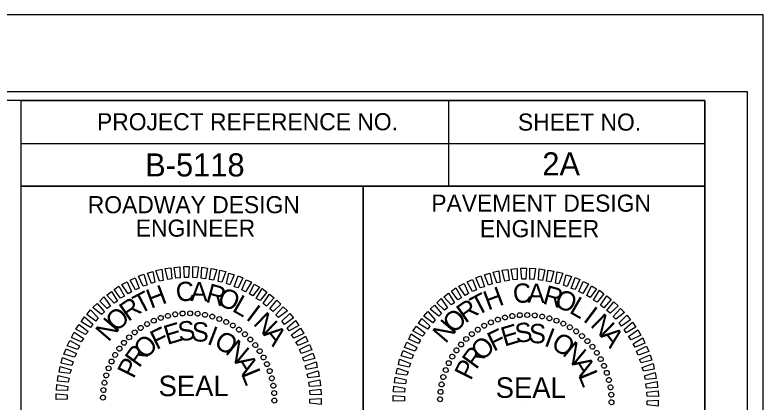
# Model space of a CAD drawing. Extents: x 575722 to 576066, y -53107 to -52774.
# Drawn here: x 575943.89 to 575965.78, y -53008.18 to -52996.87 of the extents above; entities that cross this region are included whole.
import ezdxf

# ---------------------------------------------------------------- set-up
doc = ezdxf.new("R2010")
doc.units = 0
for name, color, linetype in [('Sheet Cutting Line CELL', 7, 'Continuous'), ('Sheet Data Field CELL', 7, 'Continuous'), ('Sheet PE Seal Cell', 7, 'Continuous'), ('Sheet Plot Border Inside CELL', 7, 'Continuous'), ('Sheet Plot Border Outside CELL', 7, 'Continuous'), ('Sheet Professional Seal CELL', 7, 'Continuous'), ('Sheet Typical CELL', 7, 'Continuous')]:
    doc.layers.add(name, color=color, linetype=linetype)

msp = doc.modelspace()

# ---------------------------------------------------------------- linework, layer by layer
at = {"layer": 'Sheet Cutting Line CELL'}
msp.add_line((575965.78, -52996.867), (575797.38, -52996.867), dxfattribs=at)
at = {"layer": 'Sheet PE Seal Cell'}
for p, q in [((575958.019, -53005.768), (575958.019, -53005.768)), ((575958.229, -53005.708), (575958.229, -53005.708)), ((575958.449, -53005.668), (575958.449, -53005.668)), ((575958.664, -53005.638), (575958.664, -53005.638)), ((575958.884, -53005.633), (575958.884, -53005.633)), ((575959.104, -53005.648), (575959.104, -53005.648)), ((575959.319, -53005.683), (575959.319, -53005.683)), ((575959.529, -53005.728), (575959.529, -53005.728)), ((575957.624, -53005.948), (575957.624, -53005.948)), ((575957.819, -53005.848), (575957.819, -53005.848)), ((575959.739, -53005.798), (575959.739, -53005.798)), ((575959.939, -53005.888), (575959.939, -53005.888)), ((575957.259, -53006.188), (575957.259, -53006.188)), ((575957.434, -53006.063), (575957.434, -53006.063)), ((575960.134, -53005.988), (575960.134, -53005.988)), ((575960.314, -53006.113), (575960.314, -53006.113)), ((575957.094, -53006.338), (575957.094, -53006.338)), ((575960.489, -53006.248), (575960.489, -53006.248)), ((575960.644, -53006.398), (575960.644, -53006.398)), ((575956.944, -53006.493), (575956.944, -53006.493)), ((575960.794, -53006.563), (575960.794, -53006.563)), ((575956.684, -53006.848), (575956.684, -53006.848)), ((575956.809, -53006.668), (575956.809, -53006.668)), ((575960.919, -53006.738), (575960.919, -53006.738)), ((575956.584, -53007.043), (575956.584, -53007.043)), ((575961.034, -53006.928), (575961.034, -53006.928)), ((575956.494, -53007.243), (575956.494, -53007.243)), ((575961.134, -53007.123), (575961.134, -53007.123)), ((575956.424, -53007.453), (575956.424, -53007.453)), ((575961.214, -53007.323), (575961.214, -53007.323)), ((575956.379, -53007.663), (575956.379, -53007.663)), ((575961.274, -53007.533), (575961.274, -53007.533)), ((575956.344, -53007.878), (575956.344, -53007.878)), ((575961.314, -53007.753), (575961.314, -53007.753)), ((575956.329, -53008.098), (575956.329, -53008.098)), ((575958.839, -53008.143), (575958.839, -53008.143)), ((575961.344, -53007.968), (575961.344, -53007.968))]:
    msp.add_line(p, q, dxfattribs=at)
for points in [[(575957.749, -53004.763), (575957.634, -53004.463), (575957.789, -53004.418), (575957.854, -53004.728)], [(575957.989, -53004.698), (575957.884, -53004.383), (575958.054, -53004.348), (575958.094, -53004.673)], [(575958.229, -53004.643), (575958.149, -53004.323), (575958.314, -53004.308), (575958.349, -53004.628)], [(575958.469, -53004.613), (575958.414, -53004.293), (575958.584, -53004.273), (575958.589, -53004.598)], [(575958.719, -53004.588), (575958.694, -53004.263), (575958.859, -53004.268), (575958.839, -53004.593)], [(575958.959, -53004.593), (575958.959, -53004.268), (575959.124, -53004.273), (575959.079, -53004.598)], [(575959.209, -53004.608), (575959.229, -53004.283), (575959.394, -53004.313), (575959.329, -53004.628)], [(575959.449, -53004.648), (575959.494, -53004.328), (575959.659, -53004.353), (575959.569, -53004.663)], [(575959.704, -53004.703), (575959.754, -53004.378), (575959.924, -53004.418), (575959.809, -53004.728)], [(575957.284, -53004.948), (575957.124, -53004.668), (575957.279, -53004.598), (575957.394, -53004.903)], [(575957.504, -53004.843), (575957.374, -53004.553), (575957.524, -53004.493), (575957.629, -53004.813)], [(575959.944, -53004.768), (575960.019, -53004.458), (575960.174, -53004.508), (575960.049, -53004.803)], [(575960.169, -53004.858), (575960.284, -53004.543), (575960.424, -53004.603), (575960.284, -53004.893)], [(575960.394, -53004.953), (575960.519, -53004.658), (575960.674, -53004.728), (575960.504, -53005.008)], [(575956.849, -53005.193), (575956.664, -53004.938), (575956.794, -53004.843), (575956.959, -53005.133)], [(575957.069, -53005.068), (575956.884, -53004.798), (575957.039, -53004.718), (575957.164, -53005.008)], [(575960.624, -53005.068), (575960.759, -53004.783), (575960.909, -53004.868), (575960.719, -53005.128)], [(575956.659, -53005.343), (575956.444, -53005.103), (575956.579, -53004.998), (575956.754, -53005.278)], [(575960.819, -53005.203), (575960.994, -53004.913), (575961.124, -53005.018), (575960.929, -53005.263)], [(575961.024, -53005.353), (575961.209, -53005.078), (575961.339, -53005.188), (575961.119, -53005.423)], [(575956.459, -53005.498), (575956.239, -53005.278), (575956.359, -53005.158), (575956.554, -53005.428)], [(575961.214, -53005.508), (575961.419, -53005.248), (575961.539, -53005.368), (575961.309, -53005.583)], [(575956.119, -53005.863), (575955.859, -53005.668), (575955.969, -53005.538), (575956.189, -53005.773)], [(575956.294, -53005.673), (575956.039, -53005.468), (575956.164, -53005.353), (575956.374, -53005.593)], [(575961.394, -53005.683), (575961.609, -53005.448), (575961.729, -53005.568), (575961.469, -53005.763)], [(575955.969, -53006.053), (575955.699, -53005.883), (575955.794, -53005.738), (575956.034, -53005.958)], [(575961.569, -53005.863), (575961.799, -53005.638), (575961.904, -53005.773), (575961.639, -53005.963)], [(575955.819, -53006.253), (575955.539, -53006.103), (575955.639, -53005.963), (575955.899, -53006.163)], [(575961.719, -53006.058), (575961.964, -53005.848), (575962.059, -53005.993), (575961.779, -53006.153)], [(575955.699, -53006.468), (575955.414, -53006.343), (575955.489, -53006.188), (575955.759, -53006.373)], [(575961.849, -53006.263), (575962.114, -53006.073), (575962.209, -53006.223), (575961.919, -53006.363)], [(575961.979, -53006.483), (575962.259, -53006.308), (575962.324, -53006.463), (575962.039, -53006.578)], [(575955.599, -53006.698), (575955.289, -53006.583), (575955.364, -53006.428), (575955.649, -53006.588)], [(575962.079, -53006.698), (575962.374, -53006.548), (575962.439, -53006.708), (575962.129, -53006.808)], [(575955.499, -53006.918), (575955.189, -53006.828), (575955.254, -53006.673), (575955.554, -53006.813)], [(575962.169, -53006.933), (575962.474, -53006.803), (575962.529, -53006.958), (575962.219, -53007.038)], [(575955.424, -53007.158), (575955.114, -53007.093), (575955.149, -53006.928), (575955.464, -53007.053)], [(575962.249, -53007.173), (575962.569, -53007.058), (575962.599, -53007.223), (575962.284, -53007.278)], [(575955.359, -53007.398), (575955.049, -53007.358), (575955.084, -53007.188), (575955.399, -53007.293)], [(575955.319, -53007.653), (575954.999, -53007.623), (575955.019, -53007.453), (575955.344, -53007.533)], [(575962.309, -53007.413), (575962.624, -53007.318), (575962.654, -53007.488), (575962.339, -53007.518)], [(575955.294, -53007.893), (575954.969, -53007.883), (575954.979, -53007.718), (575955.304, -53007.773)], [(575962.354, -53007.653), (575962.679, -53007.583), (575962.694, -53007.753), (575962.374, -53007.773)], [(575962.384, -53007.893), (575962.709, -53007.853), (575962.719, -53008.023), (575962.394, -53008.013)], [(575955.289, -53008.143), (575954.964, -53008.158), (575954.964, -53007.988), (575955.289, -53008.023)], [(575962.389, -53008.143), (575962.714, -53008.128), (575962.714, -53008.298), (575962.389, -53008.263)]]:
    msp.add_lwpolyline(points, close=True, dxfattribs=at)
for centre, major_axis in [((575958.022, -53005.772), (-0.0234, 0.0681)), ((575958.232, -53005.71), (-0.0174, 0.0699)), ((575958.447, -53005.666), (-0.0113, 0.0711)), ((575958.664, -53005.641), (-0.005, 0.0718)), ((575958.883, -53005.636), (0.0013, 0.072)), ((575959.101, -53005.649), (0.0075, 0.0716)), ((575959.317, -53005.681), (0.0137, 0.0707)), ((575959.53, -53005.733), (0.0198, 0.0692)), ((575959.738, -53005.802), (0.0258, 0.0672)), ((575957.436, -53006.064), (-0.0403, 0.0597)), ((575957.623, -53005.95), (-0.0349, 0.063)), ((575957.819, -53005.852), (-0.0293, 0.0658)), ((575959.938, -53005.889), (0.0316, 0.0647)), ((575960.131, -53005.994), (0.0371, 0.0617)), ((575957.261, -53006.194), (-0.0453, 0.056)), ((575960.313, -53006.114), (0.0423, 0.0582)), ((575960.484, -53006.251), (0.0472, 0.0543)), ((575956.946, -53006.498), (-0.0543, 0.0472)), ((575957.097, -53006.339), (-0.05, 0.0518)), ((575960.643, -53006.401), (0.0518, 0.05)), ((575956.81, -53006.669), (-0.0582, 0.0423)), ((575960.788, -53006.565), (0.056, 0.0453)), ((575956.689, -53006.852), (-0.0617, 0.0371)), ((575960.918, -53006.741), (0.0597, 0.0403)), ((575961.032, -53006.927), (0.063, 0.0349)), ((575956.585, -53007.044), (-0.0647, 0.0316)), ((575961.13, -53007.123), (0.0658, 0.0293)), ((575956.498, -53007.245), (-0.0672, 0.0258)), ((575961.21, -53007.327), (0.0681, 0.0234)), ((575956.428, -53007.452), (-0.0692, 0.0198)), ((575961.272, -53007.537), (0.0699, 0.0174)), ((575956.377, -53007.665), (-0.0707, 0.0137)), ((575961.316, -53007.751), (0.0711, 0.0113)), ((575956.345, -53007.881), (-0.0716, 0.0075)), ((575961.341, -53007.968), (0.0718, 0.005)), ((575956.331, -53008.1), (-0.072, 0.0013)), ((575961.347, -53008.187), (0.072, -0.0013))]:
    msp.add_ellipse(centre, major_axis=major_axis, ratio=0.999708, dxfattribs=at)
at = {"layer": 'Sheet Plot Border Inside CELL'}
msp.add_lwpolyline([(575965.33, -52999.112), (575798.68, -52999.112), (575798.68, -53104.622), (575965.33, -53104.622)], close=True, dxfattribs=at)
at = {"layer": 'Sheet Plot Border Outside CELL'}
msp.add_lwpolyline([(575965.78, -52996.867), (575797.38, -52996.867), (575797.38, -53106.867), (575965.78, -53106.867)], close=True, dxfattribs=at)
at = {"layer": 'Sheet Professional Seal CELL'}
for p, q in [((575948.156, -53005.719), (575948.156, -53005.719)), ((575948.366, -53005.659), (575948.366, -53005.659)), ((575948.586, -53005.619), (575948.586, -53005.619)), ((575948.801, -53005.589), (575948.801, -53005.589)), ((575949.021, -53005.584), (575949.021, -53005.584)), ((575949.241, -53005.599), (575949.241, -53005.599)), ((575949.456, -53005.634), (575949.456, -53005.634)), ((575949.666, -53005.679), (575949.666, -53005.679)), ((575949.876, -53005.749), (575949.876, -53005.749)), ((575947.761, -53005.899), (575947.761, -53005.899)), ((575947.956, -53005.799), (575947.956, -53005.799)), ((575950.076, -53005.839), (575950.076, -53005.839)), ((575950.271, -53005.939), (575950.271, -53005.939)), ((575947.396, -53006.139), (575947.396, -53006.139)), ((575947.571, -53006.014), (575947.571, -53006.014)), ((575950.451, -53006.064), (575950.451, -53006.064)), ((575950.626, -53006.199), (575950.626, -53006.199)), ((575947.231, -53006.289), (575947.231, -53006.289)), ((575950.781, -53006.349), (575950.781, -53006.349)), ((575946.946, -53006.619), (575946.946, -53006.619)), ((575947.081, -53006.444), (575947.081, -53006.444)), ((575950.931, -53006.514), (575950.931, -53006.514)), ((575946.821, -53006.799), (575946.821, -53006.799)), ((575951.056, -53006.689), (575951.056, -53006.689)), ((575946.721, -53006.994), (575946.721, -53006.994)), ((575951.171, -53006.879), (575951.171, -53006.879)), ((575951.271, -53007.074), (575951.271, -53007.074)), ((575946.631, -53007.194), (575946.631, -53007.194)), ((575951.351, -53007.274), (575951.351, -53007.274)), ((575946.561, -53007.404), (575946.561, -53007.404)), ((575951.411, -53007.484), (575951.411, -53007.484)), ((575946.516, -53007.614), (575946.516, -53007.614)), ((575951.451, -53007.704), (575951.451, -53007.704)), ((575946.481, -53007.829), (575946.481, -53007.829)), ((575951.481, -53007.919), (575951.481, -53007.919)), ((575946.466, -53008.049), (575946.466, -53008.049)), ((575948.976, -53008.094), (575948.976, -53008.094)), ((575951.486, -53008.139), (575951.486, -53008.139))]:
    msp.add_line(p, q, dxfattribs=at)
for points in [[(575948.606, -53004.564), (575948.551, -53004.244), (575948.721, -53004.224), (575948.726, -53004.549)], [(575948.856, -53004.539), (575948.831, -53004.214), (575948.996, -53004.219), (575948.976, -53004.544)], [(575949.096, -53004.544), (575949.096, -53004.219), (575949.261, -53004.224), (575949.216, -53004.549)], [(575949.346, -53004.559), (575949.366, -53004.234), (575949.531, -53004.264), (575949.466, -53004.579)], [(575947.641, -53004.794), (575947.511, -53004.504), (575947.661, -53004.444), (575947.766, -53004.764)], [(575947.886, -53004.714), (575947.771, -53004.414), (575947.926, -53004.369), (575947.991, -53004.679)], [(575948.126, -53004.649), (575948.021, -53004.334), (575948.191, -53004.299), (575948.231, -53004.624)], [(575948.366, -53004.594), (575948.286, -53004.274), (575948.451, -53004.259), (575948.486, -53004.579)], [(575949.586, -53004.599), (575949.631, -53004.279), (575949.796, -53004.304), (575949.706, -53004.614)], [(575949.841, -53004.654), (575949.891, -53004.329), (575950.061, -53004.369), (575949.946, -53004.679)], [(575950.081, -53004.719), (575950.156, -53004.409), (575950.311, -53004.459), (575950.186, -53004.754)], [(575947.206, -53005.019), (575947.021, -53004.749), (575947.176, -53004.669), (575947.301, -53004.959)], [(575947.421, -53004.899), (575947.261, -53004.619), (575947.416, -53004.549), (575947.531, -53004.854)], [(575950.306, -53004.809), (575950.421, -53004.494), (575950.561, -53004.554), (575950.421, -53004.844)], [(575950.531, -53004.904), (575950.656, -53004.609), (575950.811, -53004.679), (575950.641, -53004.959)], [(575946.986, -53005.144), (575946.801, -53004.889), (575946.931, -53004.794), (575947.096, -53005.084)], [(575950.761, -53005.019), (575950.896, -53004.734), (575951.046, -53004.819), (575950.856, -53005.079)], [(575950.956, -53005.154), (575951.131, -53004.864), (575951.261, -53004.969), (575951.066, -53005.214)], [(575946.596, -53005.449), (575946.376, -53005.229), (575946.496, -53005.109), (575946.691, -53005.379)], [(575946.796, -53005.294), (575946.581, -53005.054), (575946.716, -53004.949), (575946.891, -53005.229)], [(575951.161, -53005.304), (575951.346, -53005.029), (575951.476, -53005.139), (575951.256, -53005.374)], [(575946.431, -53005.624), (575946.176, -53005.419), (575946.301, -53005.304), (575946.511, -53005.544)], [(575951.351, -53005.459), (575951.556, -53005.199), (575951.676, -53005.319), (575951.446, -53005.534)], [(575946.256, -53005.814), (575945.996, -53005.619), (575946.106, -53005.489), (575946.326, -53005.724)], [(575951.531, -53005.634), (575951.746, -53005.399), (575951.866, -53005.519), (575951.606, -53005.714)], [(575946.106, -53006.004), (575945.836, -53005.834), (575945.931, -53005.689), (575946.171, -53005.909)], [(575951.706, -53005.814), (575951.936, -53005.589), (575952.041, -53005.724), (575951.776, -53005.914)], [(575945.956, -53006.204), (575945.676, -53006.054), (575945.776, -53005.914), (575946.036, -53006.114)], [(575951.856, -53006.009), (575952.101, -53005.799), (575952.196, -53005.944), (575951.916, -53006.104)], [(575945.836, -53006.419), (575945.551, -53006.294), (575945.626, -53006.139), (575945.896, -53006.324)], [(575951.986, -53006.214), (575952.251, -53006.024), (575952.346, -53006.174), (575952.056, -53006.314)], [(575945.736, -53006.649), (575945.426, -53006.534), (575945.501, -53006.379), (575945.786, -53006.539)], [(575952.116, -53006.434), (575952.396, -53006.259), (575952.461, -53006.414), (575952.176, -53006.529)], [(575945.636, -53006.869), (575945.326, -53006.779), (575945.391, -53006.624), (575945.691, -53006.764)], [(575952.216, -53006.649), (575952.511, -53006.499), (575952.576, -53006.659), (575952.266, -53006.759)], [(575952.306, -53006.884), (575952.611, -53006.754), (575952.666, -53006.909), (575952.356, -53006.989)], [(575945.561, -53007.109), (575945.251, -53007.044), (575945.286, -53006.879), (575945.601, -53007.004)], [(575952.386, -53007.124), (575952.706, -53007.009), (575952.736, -53007.174), (575952.421, -53007.229)], [(575945.496, -53007.349), (575945.186, -53007.309), (575945.221, -53007.139), (575945.536, -53007.244)], [(575952.446, -53007.364), (575952.761, -53007.269), (575952.791, -53007.439), (575952.476, -53007.469)], [(575945.456, -53007.604), (575945.136, -53007.574), (575945.156, -53007.404), (575945.481, -53007.484)], [(575945.431, -53007.844), (575945.106, -53007.834), (575945.116, -53007.669), (575945.441, -53007.724)], [(575952.491, -53007.604), (575952.816, -53007.534), (575952.831, -53007.704), (575952.511, -53007.724)], [(575945.426, -53008.094), (575945.101, -53008.109), (575945.101, -53007.939), (575945.426, -53007.974)], [(575952.521, -53007.844), (575952.846, -53007.804), (575952.856, -53007.974), (575952.531, -53007.964)], [(575952.526, -53008.094), (575952.851, -53008.079), (575952.851, -53008.249), (575952.526, -53008.214)]]:
    msp.add_lwpolyline(points, close=True, dxfattribs=at)
for centre, major_axis in [((575948.584, -53005.617), (-0.0113, 0.0711)), ((575948.801, -53005.592), (-0.005, 0.0718)), ((575949.02, -53005.587), (0.0013, 0.072)), ((575949.238, -53005.6), (0.0075, 0.0716)), ((575947.956, -53005.803), (-0.0293, 0.0658)), ((575948.16, -53005.723), (-0.0234, 0.0681)), ((575948.37, -53005.661), (-0.0174, 0.0699)), ((575949.455, -53005.632), (0.0137, 0.0707)), ((575949.668, -53005.683), (0.0198, 0.0692)), ((575949.875, -53005.753), (0.0258, 0.0672)), ((575950.076, -53005.84), (0.0316, 0.0647)), ((575947.574, -53006.015), (-0.0403, 0.0597)), ((575947.76, -53005.901), (-0.0349, 0.063)), ((575950.268, -53005.944), (0.0371, 0.0617)), ((575950.45, -53006.065), (0.0423, 0.0582)), ((575947.398, -53006.145), (-0.0453, 0.056)), ((575950.622, -53006.201), (0.0472, 0.0543)), ((575947.083, -53006.449), (-0.0543, 0.0472)), ((575947.234, -53006.29), (-0.05, 0.0518)), ((575950.78, -53006.352), (0.0518, 0.05)), ((575946.947, -53006.62), (-0.0582, 0.0423)), ((575950.925, -53006.516), (0.056, 0.0453)), ((575951.056, -53006.692), (0.0597, 0.0403)), ((575946.827, -53006.803), (-0.0617, 0.0371)), ((575951.17, -53006.878), (0.063, 0.0349)), ((575946.722, -53006.995), (-0.0647, 0.0316)), ((575951.267, -53007.074), (0.0658, 0.0293)), ((575946.635, -53007.195), (-0.0672, 0.0258)), ((575951.348, -53007.278), (0.0681, 0.0234)), ((575946.565, -53007.403), (-0.0692, 0.0198)), ((575951.41, -53007.488), (0.0699, 0.0174)), ((575946.514, -53007.616), (-0.0707, 0.0137)), ((575951.453, -53007.702), (0.0711, 0.0113)), ((575946.482, -53007.832), (-0.0716, 0.0075)), ((575951.478, -53007.919), (0.0718, 0.005)), ((575946.469, -53008.05), (-0.072, 0.0013)), ((575951.484, -53008.138), (0.072, -0.0013))]:
    msp.add_ellipse(centre, major_axis=major_axis, ratio=0.999708, dxfattribs=at)
at = {"layer": 'Sheet Typical CELL'}
for p, q in [((575956.58, -52999.372), (575956.58, -53001.872)), ((575944.075, -53000.622), (575964.08, -53000.622)), ((575954.08, -53001.872), (575954.08, -53013.117))]:
    msp.add_line(p, q, dxfattribs=at)
for points in [[(575964.08, -52999.367), (575814.08, -52999.367), (575814.08, -53104.367), (575964.08, -53104.367)], [(575944.075, -52999.367), (575964.08, -52999.367), (575964.08, -53001.872), (575944.075, -53001.872)], [(575944.075, -53001.872), (575954.08, -53001.872), (575954.08, -53013.122), (575944.075, -53013.122)], [(575954.08, -53001.872), (575964.08, -53001.872), (575964.08, -53013.122), (575954.08, -53013.122)]]:
    msp.add_lwpolyline(points, close=True, dxfattribs=at)

# ---------------------------------------------------------------- texts
at = {"layer": 'Sheet Data Field CELL'}
for s, p in [('B-5118   ', (575947.703, -53001.587)), ('2A ', (575959.323, -53001.557))]:
    msp.add_text(s, height=0.675, dxfattribs=at).set_placement(p)
at = {"layer": 'Sheet PE Seal Cell'}
for s, height, rotation, p in [('H', 0.564, 20.6195, (575957.734, -53005.508)), ('C', 0.564, 6.2199, (575958.494, -53005.308)), ('A', 0.564, 359.0203, (575958.889, -53005.278)), ('R', 0.564, 344.6211, (575959.309, -53005.298)), ('T', 0.564, 27.8198, (575957.409, -53005.673)), ('O', 0.564, 337.4212, (575959.644, -53005.373)), ('L', 0.564, 330.2209, (575960.084, -53005.558)), ('R', 0.564, 35.0205, (575957.069, -53005.893)), ('O', 0.564, 42.2217, (575956.724, -53006.203)), ('I', 0.564, 323.0201, (575960.489, -53005.798)), ('N', 0.564, 49.4235, (575956.494, -53006.493)), ('N', 0.564, 315.8189, (575960.704, -53005.953)), ('E', 0.564, 16.6111, (575958.214, -53006.563)), ('S', 0.564, 7.2556, (575958.559, -53006.458)), ('S', 0.564, 357.9004, (575958.919, -53006.453)), ('F', 0.564, 25.967, (575957.894, -53006.713)), ('I', 0.564, 339.1896, (575959.349, -53006.523)), ('O', 0.564, 329.8335, (575959.549, -53006.593)), ('A', 0.564, 308.6172, (575960.999, -53006.248)), ('O', 0.564, 44.6812, (575957.564, -53007.008)), ('N', 0.564, 320.4766, (575959.884, -53006.793)), ('R', 0.564, 54.0397, (575957.389, -53007.253)), ('P', 0.564, 63.3989, (575957.229, -53007.573)), ('A', 0.564, 301.7603, (575960.169, -53007.053)), ('L', 0.564, 292.4008, (575960.364, -53007.398)), ('SEAL', 0.5998, 360, (575957.959, -53008.058))]:
    msp.add_text(s, height=height, rotation=rotation, dxfattribs=at).set_placement(p)
at = {"layer": 'Sheet Professional Seal CELL'}
for s, height, rotation, p in [('C', 0.564, 6.2199, (575948.631, -53005.259)), ('A', 0.564, 359.0203, (575949.026, -53005.229)), ('H', 0.564, 20.6195, (575947.871, -53005.459)), ('R', 0.564, 344.6211, (575949.446, -53005.249)), ('O', 0.564, 337.4212, (575949.781, -53005.324)), ('T', 0.564, 27.8198, (575947.546, -53005.624)), ('L', 0.564, 330.2209, (575950.221, -53005.509)), ('R', 0.564, 35.0205, (575947.206, -53005.844)), ('O', 0.564, 42.2217, (575946.861, -53006.154)), ('I', 0.564, 323.0201, (575950.626, -53005.749)), ('N', 0.564, 315.8189, (575950.841, -53005.904)), ('N', 0.564, 49.4235, (575946.631, -53006.444)), ('F', 0.564, 25.967, (575948.031, -53006.664)), ('E', 0.564, 16.6111, (575948.351, -53006.514)), ('S', 0.564, 7.2556, (575948.696, -53006.409)), ('S', 0.564, 357.9004, (575949.056, -53006.404)), ('I', 0.564, 339.1896, (575949.486, -53006.474)), ('O', 0.564, 329.8335, (575949.686, -53006.544)), ('A', 0.564, 308.6172, (575951.136, -53006.199)), ('O', 0.564, 44.6812, (575947.701, -53006.959)), ('N', 0.564, 320.4766, (575950.021, -53006.744)), ('R', 0.564, 54.0397, (575947.526, -53007.204)), ('P', 0.564, 63.3989, (575947.366, -53007.524)), ('A', 0.564, 301.7603, (575950.306, -53007.004)), ('L', 0.564, 292.4008, (575950.501, -53007.349)), ('SEAL', 0.5998, 360, (575948.096, -53008.009))]:
    msp.add_text(s, height=height, rotation=rotation, dxfattribs=at).set_placement(p)
at = {"layer": 'Sheet Typical CELL'}
for s, height, p in [('PROJECT REFERENCE NO.', 0.50001, (575946.295, -53000.237)), ('SHEET NO.', 0.5, (575958.61, -53000.247)), ('ROADWAY DESIGN', 0.50001, (575946.025, -53002.662)), ('PAVEMENT DESIGN', 0.50001, (575956.075, -53002.617)), ('ENGINEER', 0.5, (575947.43, -53003.347)), ('ENGINEER', 0.5, (575957.495, -53003.362))]:
    msp.add_text(s, height=height, dxfattribs=at).set_placement(p)

doc.saveas('drawing.dxf')
